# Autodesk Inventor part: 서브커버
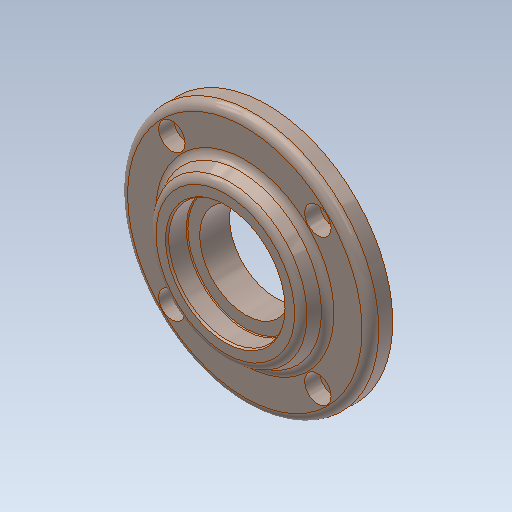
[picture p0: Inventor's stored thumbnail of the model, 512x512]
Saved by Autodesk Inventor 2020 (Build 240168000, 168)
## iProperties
Created: 2013-01
Part Number: 서브커버
Document SubType Name: Modeling
Designer: 한국산업디자인학원[gmhk.co.kr]
Density: 7.25 g/cm^3
Material: 주철
Mass: 431.687 g
Surface Area: 179.079 cm^2
Volume: 59.543 cm^3
Appearance: 강철(1)
Author: 한국산업디자인학원[gmhk.co.kr]
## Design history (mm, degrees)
sketch "스케치2"
  geometry: L1 (-45, 0)-(0, 0); L2 (-25.784, -7)-(25.784, -7) reference; L3 (0, -7)-(0, 15); L4 (-31, -23)-(-31, 0) reference; L5 (-26.5, -7)-(-26.5, -3); L6 (-26.5, -3)-(0, -3); L7 (-26.5, -7)-(-31, -7); L8 (-31, 0)-(-45, 0); L9 (-45, 0)-(-45, 8); L10 (-45, 8)-(-30, 8); L11 (-30, 8)-(-26.736, 15); L12 (-26.736, 15)-(0, 15)
  constraints: 25 end point, 6 perpendicular, 3 point on line, 1 collinear, 1 horizontal, 1 midpoint, 1 parallel, 1 vertical, 3 other
  dimensions: "d0" = 53 diameter of L5 L3; "d1" = 4 distance between parallel lines of L6 L2; "d2" = 8 distance between parallel lines of L10 L1; "d3" = 7 distance between parallel lines of L12 L10; "d4" = 60 diameter of L10.end L3; "d5" = 115 deg angle of L11 L10; "d27" = 90 diameter of L9 L3
revolve "회전1" sketch "스케치2" stored, may be unused: angle "d6" = 90 deg
hole "구멍1" diameter "d9" = 33; stored, may be unused: countersink angle "d13" = 90 deg, drill point angle "d15" = 118 deg; dims "d10" = 6, "d11" = 42, "d12" = 7.3, "d14" = 8, "d38" = 10, "d39" = 10
fillet "모깎기1" dims "d16" = 3
chamfer "모따기1" distance "d17" = 0.7; stored, may be unused: second distance "d18" = 2, angle "d19" = 30 deg
sketch "스케치3"
  geometry: C1 r 2.067 at (26.163, 26.163) reference; 1 further point
hole "구멍2" sketch "스케치3" at (26.163, 26.163) diameter "d20" = 5.4; stored, may be unused: countersink angle "d24" = 90 deg, drill point angle "d26" = 118 deg; dims "d21" = 6, "d22" = 9.5, "d23" = 5.5, "d25" = 8
fillet "모깎기2" dims "d31" = 0.3
fillet "모깎기3" dims "d32" = 3
chamfer "모따기2" distance "d35" = 1; stored, may be unused: second distance "d36" = 2, angle "d37" = 45 deg
node "솔리드1"
pattern_circular "원형 패턴1" dims angle "d29" = 360 deg
node "참조3"
